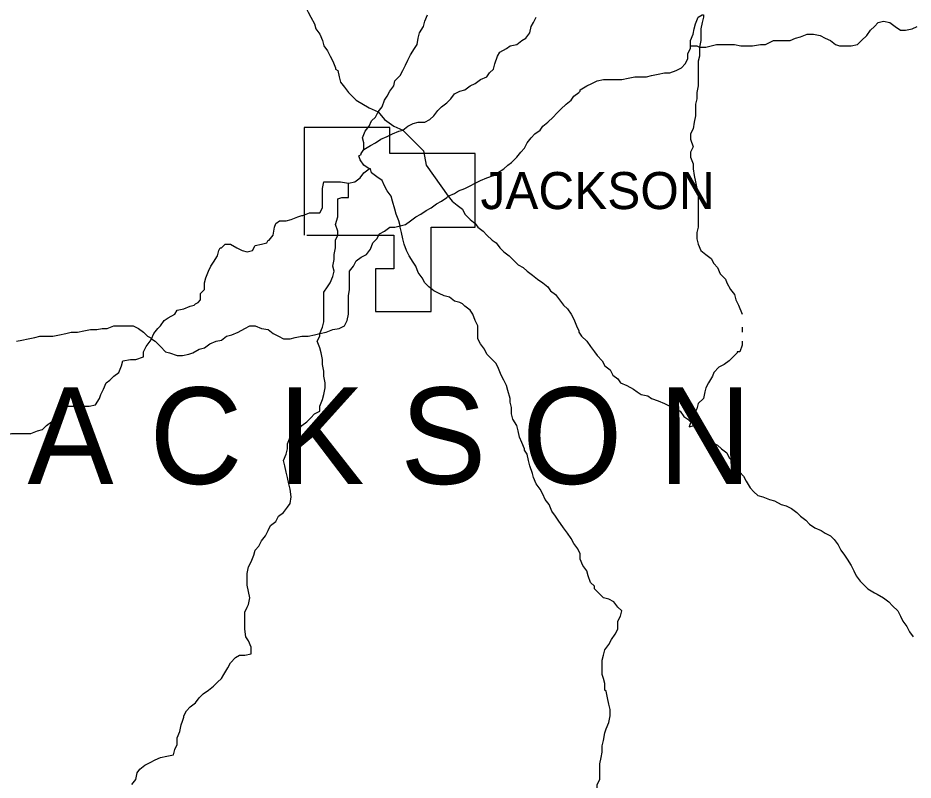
# Model space of a CAD drawing. Extents: x 0 to 34, y 0 to 22.
# Drawn here: x 6.966 to 7.908, y 17.259 to 18.061 of the extents above; entities that cross this region are included whole.
import ezdxf

# ---------------------------------------------------------------- set-up
doc = ezdxf.new("R2010")
doc.units = 0
doc.layers.add('Default', color=7, linetype='Continuous')
doc.layers.add('TR_Turning_Path1', color=7, linetype='Continuous')

msp = doc.modelspace()

# ---------------------------------------------------------------- linework, layer by layer
at = {"layer": 'Default'}
for points in [[(7.24561, 18.10212), (7.2497, 18.09803), (7.25379, 18.09257), (7.25788, 18.08848), (7.26333, 18.08167), (7.26469, 18.07758), (7.26878, 18.07212), (7.27151, 18.06667), (7.27424, 18.06122), (7.27833, 18.0544), (7.27969, 18.04895), (7.28378, 18.04349), (7.28651, 18.03667), (7.28787, 18.03122), (7.29196, 18.02577), (7.29469, 18.02031), (7.29742, 18.01486), (7.30014, 18.00804), (7.30014, 18.00668), (7.30287, 18.00532), (7.30287, 18.00532)], [(7.32878, 17.93442), (7.3315, 17.94124), (7.33559, 17.94669), (7.33832, 17.95214), (7.34241, 17.95623), (7.34514, 17.96169), (7.34923, 17.96714), (7.35195, 17.97396), (7.35468, 17.97805), (7.35741, 17.9835), (7.3615, 17.98895), (7.36286, 17.99441), (7.36831, 17.99986), (7.37104, 18.00532), (7.37377, 18.01077), (7.37649, 18.01622), (7.37922, 18.02168), (7.38331, 18.02849), (7.38604, 18.03258), (7.3874, 18.0394), (7.38877, 18.04486), (7.39286, 18.05167), (7.39422, 18.05713), (7.39695, 18.06394)], [(7.33014, 17.92215), (7.33696, 17.92624), (7.34241, 17.92896), (7.34786, 17.93305), (7.35468, 17.93578), (7.36013, 17.93851), (7.36695, 17.94124), (7.37104, 17.9426), (7.37649, 17.94669), (7.38195, 17.94942), (7.3874, 17.95078), (7.39422, 17.95078), (7.39967, 17.95351), (7.40376, 17.9576), (7.40785, 17.96305), (7.41194, 17.96714), (7.4174, 17.97123), (7.42149, 17.97532), (7.42558, 17.98077), (7.43103, 17.9835), (7.43649, 17.98486), (7.44194, 17.98895), (7.44739, 17.99168), (7.45285, 17.99577), (7.45966, 17.9985), (7.46239, 18.00259), (7.46648, 18.00668), (7.46784, 18.01213), (7.47057, 18.02031), (7.4733, 18.0244), (7.48011, 18.02849), (7.48421, 18.03122), (7.49102, 18.03258), (7.49648, 18.03667), (7.50057, 18.0394), (7.50466, 18.04486), (7.50602, 18.05167), (7.50875, 18.05576), (7.51147, 18.06122)], [(7.67372, 18.03122), (7.67372, 18.03667), (7.67645, 18.04349), (7.67781, 18.04895), (7.67917, 18.0544), (7.6819, 18.06122), (7.68599, 18.06394), (7.68735, 18.06394)], [(7.68735, 18.06394), (7.68735, 18.06122), (7.68599, 18.05576), (7.68463, 18.04895), (7.68463, 18.04349), (7.68463, 18.03667), (7.68326, 18.02986)], [(7.80325, 18.04349), (7.81006, 18.04213), (7.81552, 18.0394), (7.82097, 18.03667), (7.82642, 18.03258), (7.83051, 18.03122), (7.83733, 18.03122), (7.84278, 18.03122), (7.8496, 18.03258), (7.85369, 18.03667), (7.85915, 18.04213), (7.86324, 18.04758), (7.86733, 18.05167), (7.87142, 18.05576), (7.87687, 18.05713), (7.88369, 18.05576), (7.88914, 18.05167), (7.89459, 18.04758), (7.90005, 18.04758), (7.90687, 18.04895), (7.91232, 18.05167)], [(7.68326, 18.02986), (7.69008, 18.02986), (7.69554, 18.03122), (7.70099, 18.03258), (7.70781, 18.03258), (7.71462, 18.03258), (7.72008, 18.03258), (7.72689, 18.03122), (7.73235, 18.03122), (7.73916, 18.03122), (7.74735, 18.03258), (7.7528, 18.03258), (7.76098, 18.03667), (7.76507, 18.03667), (7.77189, 18.03667), (7.7787, 18.03667), (7.78416, 18.0394), (7.78961, 18.04076), (7.79643, 18.04349), (7.80188, 18.04349), (7.80325, 18.04349), (7.80325, 18.04349)], [(7.55783, 17.98486), (7.56465, 17.98895), (7.5701, 17.99168), (7.57555, 17.99441), (7.58237, 17.99577), (7.58919, 17.99577), (7.59464, 17.99577), (7.60146, 17.99577), (7.60828, 17.99714), (7.61509, 17.9985), (7.62191, 17.9985), (7.62736, 17.9985), (7.63282, 17.99986), (7.63964, 18.00123), (7.64645, 18.00259), (7.65191, 18.00259), (7.65872, 18.00532), (7.66418, 18.00804), (7.66827, 18.01213), (7.67099, 18.01759), (7.67099, 18.02304), (7.67372, 18.02849), (7.67372, 18.03122)], [(7.55783, 17.98486), (7.56465, 17.98895), (7.5701, 17.99168), (7.57555, 17.99441), (7.58237, 17.99577), (7.58919, 17.99577), (7.59464, 17.99577), (7.60146, 17.99577), (7.60828, 17.99714), (7.61509, 17.9985), (7.62191, 17.9985), (7.62736, 17.9985), (7.63282, 17.99986), (7.63964, 18.00123), (7.64645, 18.00259), (7.65191, 18.00259), (7.65872, 18.00532), (7.66418, 18.00804), (7.66827, 18.01213), (7.67099, 18.01759), (7.67099, 18.02304), (7.67372, 18.02849), (7.67372, 18.03122)], [(7.67372, 18.03122), (7.68054, 18.03122), (7.68326, 18.02986)], [(7.68326, 18.02986), (7.68326, 18.02849), (7.68326, 18.02031), (7.6819, 18.01486), (7.6819, 18.00804), (7.6819, 18.00259), (7.6819, 17.99577), (7.6819, 17.98895), (7.68054, 17.98214), (7.68054, 17.97532), (7.67917, 17.96987), (7.67917, 17.96305), (7.67917, 17.9576), (7.67781, 17.95078), (7.67645, 17.94396), (7.67372, 17.93851), (7.67372, 17.93305), (7.67645, 17.92487), (7.67372, 17.91942), (7.67372, 17.91397), (7.67645, 17.90715), (7.67645, 17.9017), (7.67781, 17.89488), (7.67917, 17.88806), (7.68054, 17.88124)], [(7.30287, 18.00532), (7.30423, 17.9985), (7.3056, 17.99305), (7.30969, 17.98759), (7.31378, 17.98214), (7.32196, 17.97396), (7.33559, 17.96578), (7.34514, 17.96169), (7.35195, 17.95351), (7.3615, 17.94669), (7.37104, 17.9426), (7.39286, 17.92078), (7.39558, 17.90579), (7.41876, 17.87306)], [(7.41876, 17.87306), (7.42558, 17.87579), (7.42967, 17.87852), (7.43649, 17.88124), (7.44194, 17.88397), (7.44739, 17.8867), (7.45285, 17.88943), (7.45966, 17.89215), (7.46648, 17.89488), (7.47057, 17.89761), (7.47739, 17.9017), (7.48148, 17.90579), (7.48557, 17.90851), (7.49102, 17.91397), (7.49511, 17.91942), (7.4992, 17.92351), (7.50193, 17.92896), (7.50602, 17.93442), (7.51011, 17.93851), (7.51556, 17.9426), (7.51829, 17.94669), (7.52374, 17.95078), (7.5292, 17.95623), (7.53329, 17.96032), (7.53738, 17.96441), (7.54283, 17.96987), (7.54829, 17.97396), (7.55101, 17.97805), (7.55647, 17.98214), (7.55783, 17.9835), (7.55783, 17.98486)], [(7.41876, 17.87306), (7.42558, 17.87579), (7.42967, 17.87852), (7.43649, 17.88124), (7.44194, 17.88397), (7.44739, 17.8867), (7.45285, 17.88943), (7.45966, 17.89215), (7.46648, 17.89488), (7.47057, 17.89761), (7.47739, 17.9017), (7.48148, 17.90579), (7.48557, 17.90851), (7.49102, 17.91397), (7.49511, 17.91942), (7.4992, 17.92351), (7.50193, 17.92896), (7.50602, 17.93442), (7.51011, 17.93851), (7.51556, 17.9426), (7.51829, 17.94669), (7.52374, 17.95078), (7.5292, 17.95623), (7.53329, 17.96032), (7.53738, 17.96441), (7.54283, 17.96987), (7.54829, 17.97396), (7.55101, 17.97805), (7.55647, 17.98214), (7.55783, 17.9835), (7.55783, 17.98486)], [(7.27015, 17.83216), (7.3615, 17.83216), (7.3615, 17.79671), (7.34241, 17.79671), (7.34241, 17.75172), (7.40104, 17.75172), (7.40104, 17.84034), (7.44739, 17.84034), (7.44739, 17.91806), (7.35741, 17.91806), (7.35741, 17.94533), (7.26742, 17.94533), (7.26742, 17.83216)], [(7.33014, 17.92215), (7.33014, 17.92896), (7.32878, 17.93442)], [(7.33559, 17.9017), (7.33014, 17.90579), (7.32605, 17.91124), (7.32468, 17.91533), (7.32741, 17.91669)], [(7.32741, 17.91669), (7.32741, 17.91806), (7.33014, 17.92215)], [(7.31378, 17.8867), (7.32059, 17.88806), (7.32605, 17.89215), (7.33014, 17.89761), (7.33559, 17.9017), (7.33559, 17.9017)], [(7.36831, 17.84171), (7.36695, 17.84716), (7.36422, 17.85398), (7.36286, 17.85943), (7.36013, 17.86761), (7.35877, 17.87306), (7.35468, 17.87852), (7.35195, 17.88397), (7.34923, 17.88943), (7.34377, 17.89352), (7.33832, 17.89761), (7.33696, 17.9017), (7.33559, 17.9017)], [(7.26606, 17.85261), (7.27287, 17.85534), (7.27833, 17.85534), (7.28378, 17.85534), (7.28651, 17.86079), (7.28651, 17.86761), (7.28651, 17.87443), (7.28651, 17.88124), (7.28787, 17.88806), (7.29469, 17.88806), (7.30014, 17.88806), (7.3056, 17.88806), (7.31378, 17.8867)], [(7.28378, 17.72854), (7.28651, 17.73536), (7.28787, 17.74081), (7.28787, 17.74763), (7.28787, 17.75445), (7.28787, 17.76126), (7.28787, 17.76672), (7.28787, 17.77217), (7.29196, 17.77762), (7.29469, 17.78171), (7.29742, 17.78853), (7.29878, 17.79399), (7.29742, 17.79944), (7.29878, 17.80626), (7.29878, 17.81171), (7.30014, 17.81853), (7.30014, 17.82671), (7.30287, 17.83216), (7.30287, 17.83625), (7.30014, 17.84307), (7.30287, 17.85125), (7.30287, 17.85807), (7.30287, 17.86352), (7.30287, 17.87034), (7.30696, 17.8717), (7.31378, 17.8717), (7.31378, 17.87715), (7.31378, 17.88397), (7.31378, 17.88533), (7.31378, 17.8867)], [(7.68054, 17.88124), (7.68054, 17.88124), (7.6819, 17.87852), (7.6819, 17.87306), (7.6819, 17.86488), (7.6819, 17.85943), (7.6819, 17.85398), (7.6819, 17.84716), (7.6819, 17.84034), (7.68054, 17.83489), (7.68054, 17.82807), (7.6819, 17.82262), (7.68463, 17.8158), (7.69008, 17.81171), (7.69554, 17.80762), (7.69826, 17.80217), (7.70235, 17.79808), (7.70508, 17.79126), (7.71053, 17.78581), (7.7119, 17.78171), (7.71599, 17.7749), (7.72008, 17.76944), (7.72144, 17.76399), (7.72417, 17.75854), (7.72826, 17.74899)], [(7.36831, 17.84171), (7.37377, 17.84307), (7.37922, 17.84716), (7.38468, 17.85125), (7.39013, 17.85398), (7.39558, 17.85807), (7.40104, 17.86079), (7.40649, 17.86488), (7.41194, 17.86761), (7.4174, 17.8717), (7.41876, 17.87306)], [(7.36831, 17.84171), (7.37377, 17.84307), (7.37922, 17.84716), (7.38468, 17.85125), (7.39013, 17.85398), (7.39558, 17.85807), (7.40104, 17.86079), (7.40649, 17.86488), (7.41194, 17.86761), (7.4174, 17.8717), (7.41876, 17.87306)], [(7.41876, 17.87306), (7.42285, 17.86761), (7.4283, 17.86352), (7.43376, 17.85943), (7.43649, 17.85398), (7.44194, 17.84852), (7.44739, 17.84443), (7.45012, 17.84034), (7.45557, 17.83625), (7.45966, 17.83216), (7.46512, 17.82671), (7.46921, 17.82398), (7.4733, 17.81853), (7.47739, 17.81444), (7.48284, 17.81035), (7.4883, 17.80489), (7.49239, 17.8008), (7.49784, 17.79808), (7.50193, 17.79399), (7.50738, 17.7899), (7.51284, 17.78581), (7.51829, 17.78171), (7.52374, 17.77762), (7.52647, 17.77353), (7.53192, 17.76944), (7.53602, 17.76399), (7.54011, 17.75854), (7.5442, 17.75445), (7.54829, 17.74899), (7.55101, 17.74354), (7.55374, 17.73672), (7.55647, 17.73127), (7.55647, 17.7299)], [(7.23061, 17.82671), (7.2347, 17.83216), (7.23606, 17.84034), (7.23743, 17.84443), (7.24152, 17.84716), (7.24833, 17.84716), (7.25379, 17.84852), (7.2606, 17.85125), (7.26469, 17.85261), (7.26606, 17.85261)], [(7.28378, 17.72854), (7.2906, 17.7299), (7.29742, 17.73263), (7.30423, 17.734), (7.30969, 17.73672), (7.31241, 17.74218), (7.31378, 17.74899), (7.31378, 17.75445), (7.31378, 17.76126), (7.31378, 17.76808), (7.31514, 17.7749), (7.31514, 17.78171), (7.31514, 17.78717), (7.31514, 17.79399), (7.31923, 17.79944), (7.32196, 17.80489), (7.32741, 17.80898), (7.33287, 17.81171), (7.33696, 17.81716), (7.33968, 17.82398), (7.34377, 17.82807), (7.3465, 17.83352), (7.35195, 17.83625), (7.35741, 17.84034), (7.36286, 17.84034), (7.36831, 17.84171), (7.36831, 17.84171)], [(7.28378, 17.72854), (7.2906, 17.7299), (7.29742, 17.73263), (7.30423, 17.734), (7.30969, 17.73672), (7.31241, 17.74218), (7.31378, 17.74899), (7.31378, 17.75445), (7.31378, 17.76126), (7.31378, 17.76808), (7.31514, 17.7749), (7.31514, 17.78171), (7.31514, 17.78717), (7.31514, 17.79399), (7.31923, 17.79944), (7.32196, 17.80489), (7.32741, 17.80898), (7.33287, 17.81171), (7.33696, 17.81716), (7.33968, 17.82398), (7.34377, 17.82807), (7.3465, 17.83352), (7.35195, 17.83625), (7.35741, 17.84034), (7.36286, 17.84034), (7.36831, 17.84171), (7.36831, 17.84171)], [(7.43103, 17.76126), (7.42558, 17.76263), (7.42012, 17.76672), (7.41467, 17.76808), (7.40922, 17.77081), (7.40376, 17.77353), (7.39831, 17.77762), (7.39422, 17.78171), (7.39149, 17.78717), (7.3874, 17.79262), (7.38468, 17.79944), (7.38195, 17.80353), (7.37786, 17.81035), (7.37513, 17.8158), (7.3724, 17.82262), (7.37104, 17.82807), (7.36968, 17.83489), (7.36831, 17.84034), (7.36831, 17.84171)], [(7.18016, 17.81853), (7.18425, 17.82262), (7.18971, 17.82262), (7.19652, 17.81853), (7.20198, 17.8158), (7.20743, 17.81444), (7.21288, 17.8158), (7.21561, 17.82125), (7.22243, 17.82262), (7.22788, 17.82398), (7.22925, 17.82671), (7.23061, 17.82671)], [(7.15562, 17.76126), (7.15835, 17.76399), (7.15835, 17.77081), (7.16244, 17.7749), (7.16244, 17.78171), (7.1638, 17.78717), (7.16653, 17.79399), (7.16925, 17.79944), (7.17198, 17.80353), (7.17607, 17.81035), (7.17744, 17.8158), (7.1788, 17.81853), (7.18016, 17.81853)], [(7.10654, 17.72309), (7.10926, 17.72854), (7.11335, 17.734), (7.11608, 17.73672), (7.12017, 17.74218), (7.12426, 17.7449), (7.13108, 17.74899), (7.13381, 17.75308), (7.14062, 17.75445), (7.14744, 17.75717), (7.15153, 17.75854), (7.15289, 17.7599), (7.15562, 17.76126)], [(7.4992, 17.6072), (7.49648, 17.61401), (7.49375, 17.61947), (7.49239, 17.62628), (7.49102, 17.63174), (7.48693, 17.63856), (7.48557, 17.64401), (7.48557, 17.65083), (7.48421, 17.65628), (7.48421, 17.66037), (7.48148, 17.66855), (7.48011, 17.674), (7.47739, 17.67946), (7.47466, 17.68491), (7.47193, 17.69173), (7.46921, 17.69718), (7.46512, 17.70127), (7.45966, 17.70673), (7.45694, 17.71218), (7.45285, 17.71763), (7.45012, 17.72309), (7.45012, 17.7299), (7.45012, 17.73672), (7.44739, 17.74218), (7.44467, 17.74899), (7.44194, 17.75308), (7.43649, 17.75717), (7.43376, 17.7599), (7.43103, 17.76126)], [(6.96474, 17.72036), (6.9702, 17.72172), (6.97701, 17.72309), (6.98383, 17.72445), (6.98928, 17.72581), (6.9961, 17.72581), (7.00292, 17.72581), (7.00973, 17.72718), (7.01655, 17.72854), (7.02201, 17.7299), (7.02882, 17.7299), (7.03564, 17.73127), (7.04246, 17.73263), (7.04927, 17.73263), (7.05473, 17.734), (7.06018, 17.734), (7.067, 17.73672), (7.07382, 17.73672), (7.082, 17.73672), (7.08745, 17.73672), (7.0929, 17.734), (7.09836, 17.7299), (7.10245, 17.72581), (7.10517, 17.72445), (7.10654, 17.72309)], [(6.96474, 17.72036), (6.9702, 17.72172), (6.97701, 17.72309), (6.98383, 17.72445), (6.98928, 17.72581), (6.9961, 17.72581), (7.00292, 17.72581), (7.00973, 17.72718), (7.01655, 17.72854), (7.02201, 17.7299), (7.02882, 17.7299), (7.03564, 17.73127), (7.04246, 17.73263), (7.04927, 17.73263), (7.05473, 17.734), (7.06018, 17.734), (7.067, 17.73672), (7.07382, 17.73672), (7.082, 17.73672), (7.08745, 17.73672), (7.0929, 17.734), (7.09836, 17.7299), (7.10245, 17.72581), (7.10517, 17.72445), (7.10654, 17.72309)], [(7.10654, 17.72309), (7.11063, 17.72036), (7.11608, 17.71491), (7.12154, 17.70945), (7.12563, 17.70809), (7.13381, 17.70536), (7.13926, 17.70536), (7.14608, 17.70673), (7.15017, 17.70809), (7.15698, 17.71218), (7.16244, 17.71354), (7.16789, 17.71763), (7.17471, 17.72036), (7.18016, 17.72172), (7.18562, 17.72581), (7.19107, 17.72718), (7.19789, 17.7299), (7.2047, 17.734), (7.21016, 17.73672), (7.21561, 17.73672), (7.22243, 17.734), (7.22925, 17.73263), (7.2347, 17.72854), (7.24015, 17.72581), (7.24561, 17.72309), (7.25242, 17.72309), (7.25788, 17.72445), (7.26469, 17.72581), (7.27151, 17.72581), (7.27833, 17.72718), (7.28378, 17.72854), (7.28378, 17.72854)], [(7.10654, 17.72309), (7.11063, 17.72036), (7.11608, 17.71491), (7.12154, 17.70945), (7.12563, 17.70809), (7.13381, 17.70536), (7.13926, 17.70536), (7.14608, 17.70673), (7.15017, 17.70809), (7.15698, 17.71218), (7.16244, 17.71354), (7.16789, 17.71763), (7.17471, 17.72036), (7.18016, 17.72172), (7.18562, 17.72581), (7.19107, 17.72718), (7.19789, 17.7299), (7.2047, 17.734), (7.21016, 17.73672), (7.21561, 17.73672), (7.22243, 17.734), (7.22925, 17.73263), (7.2347, 17.72854), (7.24015, 17.72581), (7.24561, 17.72309), (7.25242, 17.72309), (7.25788, 17.72445), (7.26469, 17.72581), (7.27151, 17.72581), (7.27833, 17.72718), (7.28378, 17.72854), (7.28378, 17.72854)], [(7.25242, 17.56493), (7.25106, 17.57038), (7.2497, 17.5772), (7.24833, 17.58266), (7.24697, 17.58947), (7.24561, 17.59493), (7.24833, 17.60174), (7.2497, 17.6072), (7.2497, 17.61265), (7.25242, 17.61947), (7.25651, 17.62219), (7.2606, 17.62628), (7.26469, 17.63174), (7.27015, 17.63583), (7.27424, 17.63992), (7.27833, 17.64401), (7.28378, 17.64674), (7.28378, 17.65219), (7.28651, 17.65901), (7.28787, 17.66446), (7.28924, 17.67128), (7.28924, 17.67673), (7.28787, 17.68355), (7.28787, 17.689), (7.28651, 17.69582), (7.28651, 17.70127), (7.28515, 17.70809), (7.28378, 17.71354), (7.28106, 17.72036), (7.28378, 17.72581), (7.28378, 17.72854)], [(7.55647, 17.7299), (7.55919, 17.72581), (7.56465, 17.72036), (7.56874, 17.71491), (7.57283, 17.70945), (7.57555, 17.70536), (7.58101, 17.69991), (7.58373, 17.69446), (7.58919, 17.69037), (7.59192, 17.68491), (7.59737, 17.68082), (7.6001, 17.67673), (7.60691, 17.674), (7.61373, 17.66991), (7.61782, 17.66719), (7.62191, 17.66446), (7.62873, 17.6631), (7.63282, 17.66037), (7.63964, 17.65764), (7.64645, 17.65492), (7.65191, 17.65219), (7.65736, 17.64946), (7.66281, 17.64674), (7.6669, 17.64128), (7.67099, 17.63856), (7.67645, 17.6331), (7.67645, 17.6331), (7.67781, 17.63174)], [(7.72826, 17.73536), (7.72826, 17.7299)], [(7.01655, 17.65219), (7.02201, 17.65219), (7.02882, 17.65219), (7.03564, 17.65219), (7.04109, 17.65219), (7.04791, 17.65355), (7.052, 17.66037), (7.05336, 17.66446), (7.05609, 17.66991), (7.05882, 17.67673), (7.06291, 17.67946), (7.067, 17.68355), (7.07245, 17.68764), (7.07518, 17.69446), (7.07654, 17.69991), (7.08472, 17.70127), (7.09018, 17.70127), (7.09836, 17.704), (7.09836, 17.70945), (7.10108, 17.71491), (7.10517, 17.72036), (7.10654, 17.72309)], [(7.72826, 17.72036), (7.72826, 17.71627), (7.72553, 17.70945)], [(7.72553, 17.70945), (7.7228, 17.70945), (7.7228, 17.70809), (7.71871, 17.704), (7.71462, 17.69991), (7.70917, 17.69582), (7.70372, 17.69309), (7.69826, 17.68764), (7.6969, 17.68355), (7.69281, 17.67673), (7.69008, 17.67128), (7.68872, 17.66719), (7.68735, 17.66037), (7.6819, 17.65492), (7.68054, 17.64946), (7.67781, 17.64401)], [(6.9552, 17.62219), (6.95929, 17.62356), (6.96747, 17.62356), (6.97429, 17.62356), (6.97974, 17.62356), (6.98656, 17.62628), (6.99201, 17.62765), (6.9961, 17.63174), (7.00155, 17.63583), (7.00564, 17.63992), (7.00837, 17.64537), (7.01382, 17.65083), (7.01519, 17.65219), (7.01655, 17.65219)], [(7.67781, 17.64401), (7.67645, 17.63992), (7.67372, 17.63447), (7.67236, 17.63038), (7.67781, 17.63174)], [(7.67781, 17.63174), (7.6819, 17.62765), (7.68735, 17.62356), (7.69281, 17.61947), (7.6969, 17.61401), (7.70235, 17.61129), (7.70644, 17.6072), (7.7119, 17.60311), (7.71462, 17.59765), (7.71871, 17.59356), (7.72144, 17.58675), (7.72553, 17.58266), (7.72962, 17.57857), (7.73235, 17.57311), (7.73644, 17.56629), (7.74053, 17.5622), (7.74462, 17.55811), (7.75007, 17.55675), (7.75689, 17.55402), (7.76234, 17.55266), (7.76916, 17.54857), (7.77461, 17.54721), (7.77461, 17.54721)], [(7.53465, 17.53221), (7.53192, 17.5363), (7.52783, 17.54175), (7.52511, 17.54857), (7.52102, 17.55402), (7.51829, 17.55948), (7.51556, 17.56493), (7.51147, 17.57038), (7.50875, 17.5772), (7.50738, 17.58129), (7.50466, 17.58947), (7.50329, 17.59493), (7.50193, 17.60174), (7.4992, 17.60583), (7.4992, 17.6072)], [(7.20879, 17.44359), (7.21016, 17.4504), (7.20879, 17.45722), (7.20743, 17.46404), (7.20743, 17.47085), (7.20743, 17.47631), (7.20879, 17.48313), (7.21152, 17.48858), (7.21425, 17.4954), (7.21561, 17.50085), (7.2197, 17.50494), (7.22243, 17.51039), (7.22652, 17.51585), (7.22925, 17.5213), (7.23197, 17.52676), (7.23743, 17.53085), (7.24015, 17.5363), (7.24561, 17.54039), (7.2497, 17.54584), (7.25242, 17.54993), (7.25379, 17.55675), (7.25242, 17.56493), (7.25242, 17.56493)], [(7.77461, 17.54721), (7.78007, 17.54448), (7.78552, 17.54039), (7.78961, 17.5363), (7.79507, 17.53221), (7.79916, 17.52812), (7.80461, 17.52403), (7.81143, 17.5213), (7.81552, 17.51857), (7.82097, 17.51585), (7.82506, 17.51176), (7.82915, 17.5063), (7.83188, 17.50085), (7.83597, 17.4954), (7.83869, 17.49131), (7.84278, 17.48449), (7.84551, 17.47904), (7.84824, 17.47358), (7.85233, 17.46813), (7.85642, 17.46404), (7.86051, 17.45995), (7.86733, 17.45586), (7.87005, 17.45449), (7.87005, 17.45449)], [(7.57283, 17.46267), (7.56874, 17.46676), (7.56601, 17.47358), (7.56465, 17.47904), (7.56056, 17.48449), (7.55783, 17.49131), (7.55783, 17.49676), (7.5551, 17.50221), (7.55101, 17.50767), (7.54829, 17.51312), (7.5442, 17.51857), (7.54011, 17.52403), (7.53465, 17.53221), (7.53465, 17.53221)], [(7.58373, 17.3536), (7.58373, 17.36042), (7.58237, 17.36587), (7.58101, 17.36996), (7.58101, 17.37678), (7.58101, 17.38496), (7.58237, 17.39041), (7.58373, 17.39587), (7.58783, 17.40132), (7.59055, 17.40677), (7.59464, 17.41223), (7.59737, 17.41768), (7.59737, 17.42586), (7.6001, 17.43132), (7.60146, 17.43677), (7.59737, 17.44086), (7.59328, 17.44631), (7.58783, 17.44904), (7.58237, 17.4504), (7.57692, 17.45586), (7.57283, 17.45995), (7.57283, 17.45995), (7.57283, 17.46267)], [(7.58373, 17.3536), (7.58373, 17.36042), (7.58237, 17.36587), (7.58101, 17.36996), (7.58101, 17.37678), (7.58101, 17.38496), (7.58237, 17.39041), (7.58373, 17.39587), (7.58783, 17.40132), (7.59055, 17.40677), (7.59464, 17.41223), (7.59737, 17.41768), (7.59737, 17.42586), (7.6001, 17.43132), (7.60146, 17.43677), (7.59737, 17.44086), (7.59328, 17.44631), (7.58783, 17.44904), (7.58237, 17.4504), (7.57692, 17.45586), (7.57283, 17.45995), (7.57283, 17.45995), (7.57283, 17.46267)], [(7.87005, 17.45449), (7.87687, 17.4504), (7.88232, 17.44631), (7.88641, 17.44222), (7.89187, 17.43677), (7.89459, 17.43132), (7.89732, 17.42586), (7.90141, 17.42041), (7.90414, 17.41495), (7.90823, 17.4095)], [(7.14062, 17.32633), (7.14335, 17.33179), (7.14744, 17.33588), (7.15289, 17.33997), (7.15698, 17.34542), (7.16107, 17.34951), (7.16653, 17.3536), (7.17198, 17.35769), (7.17607, 17.36178), (7.18016, 17.36587), (7.18289, 17.36996), (7.18698, 17.37678), (7.18971, 17.38223), (7.19516, 17.38769), (7.19925, 17.39041), (7.2047, 17.39041), (7.21152, 17.39178), (7.21152, 17.39859), (7.20879, 17.40541), (7.20607, 17.4095), (7.2047, 17.41768), (7.2047, 17.42314), (7.2047, 17.42995), (7.2047, 17.43541), (7.20743, 17.44086), (7.20879, 17.44359), (7.20879, 17.44359), (7.20879, 17.44359)], [(7.57828, 17.27589), (7.57964, 17.2827), (7.58101, 17.28816), (7.58101, 17.29497), (7.58237, 17.30043), (7.58373, 17.30861), (7.5851, 17.3127), (7.58783, 17.31952), (7.58919, 17.32633), (7.58919, 17.33315), (7.58783, 17.3386), (7.58646, 17.34542), (7.5851, 17.35224), (7.58373, 17.3536)], [(7.08609, 17.25407), (7.09018, 17.25952), (7.09154, 17.26634), (7.09427, 17.27043), (7.09972, 17.27452), (7.10517, 17.27725), (7.11063, 17.27998), (7.11608, 17.2827), (7.1229, 17.28407), (7.12972, 17.28543), (7.13108, 17.29088), (7.13381, 17.29634), (7.13381, 17.30315), (7.13653, 17.30997), (7.1379, 17.31679), (7.13926, 17.32088), (7.14062, 17.32497), (7.14062, 17.32633)], [(7.56328, 17.19272), (7.56601, 17.19817), (7.56874, 17.20499), (7.57283, 17.21044), (7.57283, 17.21453), (7.57283, 17.22135), (7.57419, 17.22817), (7.57555, 17.23498), (7.57555, 17.2418), (7.57555, 17.24725), (7.57555, 17.25407), (7.57828, 17.25952), (7.57828, 17.26771), (7.57828, 17.27452), (7.57828, 17.27589)]]:
    msp.add_lwpolyline(points, dxfattribs=at)

# ---------------------------------------------------------------- texts
msp.add_text('JACKSON', height=0.039005, dxfattribs=at).set_placement((7.45285, 17.85943))
at = {"layer": 'TR_Turning_Path1'}
msp.add_text('J A C K S O N', height=0.1014887, dxfattribs=at).set_placement((6.87067, 17.57038))

doc.saveas('drawing.dxf')
